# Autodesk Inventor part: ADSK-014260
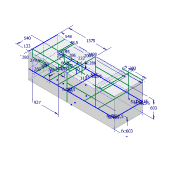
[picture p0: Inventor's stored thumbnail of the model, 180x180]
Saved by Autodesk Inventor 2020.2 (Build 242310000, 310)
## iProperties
Created: 2019-10
Part Number: ADSK-014260
Material: 1.0501 C35
Document SubType Name: Modeling
Designer: lutzd
Mass: 2.3214e+07 g
Surface Area: 141996 cm^2
Volume: 2.96097e+06 cm^3
Density: 7.84 g/cm^3
Appearance: Klar
VLDS_Profile: Default Part
VLDS_TimeStamp: 2016-07-29
VLDS_FailCnt: 0
VLDS_AcceptCnt: 0
Dimensions: 1030x1022x3080 mm
Mass: 23214,02 kg
DocNumber: ADSK-014260
Folder: 01 - Themengebiete\Simplification\01 - Packaging machine\
VDS_Category: 3D Komponenten
VDS_NumSchm: Autodesk
VLT_Material: 1.0501 C35
Title: skeleton
Author: lutzd
Revision Number: -
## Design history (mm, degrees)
sketch "Skizze1"
  geometry: L1 (-1540, -515)-(1540, -515); L2 (1540, -515)-(1540, 515); L3 (1540, 515)-(-1540, 515); L4 (-1540, 515)-(-1540, -515); L5 (-1540, -515)-(1540, 515); L6 (1540, -515)-(-1540, 515); 1 further point
  constraints: 12 end point, 2 midpoint, 2 parallel, 1 horizontal, 1 perpendicular
  dimensions: "d0" = 3080 distance of L3.end L2.end; "d1" = 1030 distance of L1.end L2.end
extrude "Extrusion1" new body sketch "Skizze1" distance "d2" = 908; taper "d3" = 0 deg
sketch "Skizze2"
  geometry: L1 (1540, 515)-(-1540, 515) reference; L2 (-1540, -515)-(1540, -515) reference; L3 (-165, 515)-(-165, -515); L4 (-1540, 515)-(-1540, -515) reference; L5 (-1540, -382)-(-165, -382); L6 (-1260, -382)-(-1260, 515); L7 (-1260, 25)-(-165, 25); L8 (-992, 25)-(-992, 515); L9 (-943.5, 25)-(-943.5, 515); 1 further point
  constraints: 12 end point, 12 point on line, 3 perpendicular, 2 horizontal, 1 vertical
  dimensions: "d4" = 1375 distance between parallel lines of L3 L4; "d5" = 133 distance between parallel lines of L5 L2; "d6" = 280 distance between parallel lines of L4 L6; "d7" = 540 distance between parallel lines of L2 L7; "d35" = 548 distance between parallel lines of L4 L8; "d36" = 48.5 distance between parallel lines of L8 L9
workplane "Arbeitsebene1"
sketch "Skizze3"
  geometry: L1 (2800, 0)-(-280, 0) reference; L2 (466, 0)-(466, -253); L3 (466, -253)-(1205, -253); L4 (1095, 0)-(1095, -253); L5 (-280, -908)-(-280, 0) reference; L6 (532.5, -203)-(735.5, -203); 3 further points
  constraints: 8 end point, 4 point on line, 3 perpendicular, 2 vertical alignment, 1 horizontal
  dimensions: "d9" = 253 distance of L2.start L2.end; "d10" = 110 distance from line of L4 L3.end; "d12" = 746 distance between parallel lines of L5 L2; "d53" = 50 distance between parallel lines of L3 L6; "d54" = 66.5 distance from line of L2 point (532.5, -253); "d55" = 203 distance of point (735.5, -253) point (532.5, -253)
workplane "Arbeitsebene2"
sketch "Skizze4"
  geometry: L1 (0, 0)-(1375, 0) reference; L2 (927, 0)-(927, -253); L3 (0, -908)-(0, 0) reference; L4 (927, -253)-(0, -253); L5 (0, 0)-(0, -253); L6 (279.5, -203)-(482.5, -203); 3 further points
  constraints: 9 end point, 3 point on line, 3 vertical alignment, 2 horizontal, 1 collinear, 1 perpendicular
  dimensions: "d14" = 927 distance between parallel lines of L3 L2; "d15" = 253 distance of L2.start L2.end (= d9); "d50" = 279.5 distance from line of L3 point (279.5, -253); "d51" = 203 distance of point (482.5, -253) point (279.5, -253); "d52" = 50 distance between parallel lines of L4 L6
sketch "Skizze5"
  geometry: L1 (1540, -515)-(1540, 515) reference; L2 (1540, 515)-(-1540, 515) reference; L3 (-1540, -515)-(1540, -515) reference; L4 (1540, 515)-(855, 515); L5 (1540, -515)-(855, -515); L6 (855, 515)-(855, -515); 1 further point
  constraints: 6 end point, 2 point on line, 1 perpendicular
  dimensions: "d16" = 685 distance between parallel lines of L1 L6
extrude "Extrusion2" join sketch "Skizze5" distance "d17" = 114; taper "d18" = 0 deg
workplane "Arbeitsebene3"
sketch "Skizze7"
  geometry: L1 (1540, 515)-(855, 515) reference; L2 (855, -515)-(1540, -515) reference; L3 (1540, 515)-(790, 515); L4 (1540, -515)-(790, -515); 1 further point
  constraints: 4 end point, 1 horizontal, 1 point on line, 1 vertical alignment
  dimensions: "d26" = 750 distance of L1.start L3.end
workplane "Arbeitsebene4"
workplane "Arbeitsebene5"
workplane "Arbeitsebene6"
workplane "Arbeitsebene7"
sketch "Skizze8"
  geometry: L1 (95, 260)-(0, 260); L2 (95, 1030)-(0, 1030); 3 further points
  constraints: 4 end point, 2 horizontal, 2 vertical alignment, 1 coincident
  dimensions: "d27" = 260 distance from line of point (0, 0) L1; "d28" = 95 distance of L2.start L2.end
sketch "Skizze9"
  geometry: L1 (95, 1030)-(0, 1030) reference; L2 (95, 260)-(0, 260) reference; 1 further point
sketch "Skizze10"
  geometry: L1 (95, 1030)-(0, 1030) reference; L2 (95, 705)-(0, 705); 2 further points
  constraints: 2 end point, 2 vertical alignment, 1 horizontal
  dimensions: "d29" = 705 distance from line of L2 point (0, 0)
sketch "Skizze11"
  geometry: L1 (95, 1030)-(0, 1030) reference; L2 (95, 705)-(0, 705) reference; 1 further point
sketch "Skizze12"
  geometry: L1 (2569, -355)-(2569, -1022); L2 (2569, -603)-(1375, -603); L3 (1375, -908)-(1375, 0); 4 further points
  constraints: 6 end point, 3 horizontal alignment, 2 point on line, 2 vertical, 1 horizontal
  dimensions: "d30" = 511 distance from line of point (3080, -1022) L1; "d33" = 603 distance from line of L2 point (3080, 0)
sketch "Skizze13"
  geometry: L1 (2395, 1022)-(2395, 355); L2 (1375, 908)-(1375, 0); L3 (1375, 603)-(2395, 603); 3 further points
  constraints: 6 end point, 2 horizontal alignment, 2 point on line, 2 vertical, 1 perpendicular
  dimensions: "d34" = 603 distance from line of point (3080, 0) L3 (= d33)
workplane "Arbeitsebene8"
sketch "Skizze14"
  geometry: L1 (1058, 515)-(1058, -515); L2 (855, 515)-(855, -515) reference; 1 further point
  constraints: 2 end point, 2 horizontal alignment, 1 vertical
  dimensions: "d56" = 203 distance between parallel lines of L2 L1
node "Volumenkörper1"
sketch "Skizze6"
  geometry: L1 (-1540, -515)-(-1540, 515) reference; L2 (1312, -515)-(1312, 515); L3 (1026, -515)-(1026, 515); L4 (804, -515)-(804, 515); L5 (518, -515)-(518, 515); L6 (-464, -515)-(-464, 515); L7 (1540, 515)-(1540, -515) reference; L8 (165, 515)-(165, -515) reference; L9 (-950, -515)-(-950, 515); L10 (-1457.5, 439)-(-1572.5, 439); L11 (-1457.5, -439)-(-1572.5, -439); L12 (247.5, 439)-(132.5, 439); L13 (247.5, -439)-(132.5, -439); 5 further points; 2 other entities
  constraints: 20 end point, 6 vertical, 4 horizontal, 4 point on line, 14 other
  dimensions: "d20" = 228 distance between parallel lines of L7 L2; "d21" = 286 distance between parallel lines of L3 L2; "d22" = 222 distance between parallel lines of L4 L3; "d23" = 286 distance between parallel lines of L5 L4 (= d21); "d24" = 2004 distance between parallel lines of L7 L6; "d25" = 2490 distance between parallel lines of L7 L9; "d38" = 76 dimension on L13; "d39" = 76 dimension on L12 (= d38); "d40" = 76 dimension on L11 (= d38); "d41" = 76 dimension on L10 (= d38); "d42" = 115 distance of L13.start L13.end; "d43" = 115 distance of L12.start L12.end (= d42); "d44" = 115 distance of L11.start L11.end (= d42); "d45" = 115 distance of L10.start L10.end (= d42); "d46" = 32.5 distance from line of L8 L12.end; "d47" = 32.5 distance from line of L8 L13.end (= d46); "d48" = 32.5 distance from line of L1 L11.end (= d46); "d49" = 32.5 distance from line of L1 L10.end (= d46)
other parameters: "d8" = 90 deg, "d13" = 90 deg, "d19" = -355, "d37" = -35
